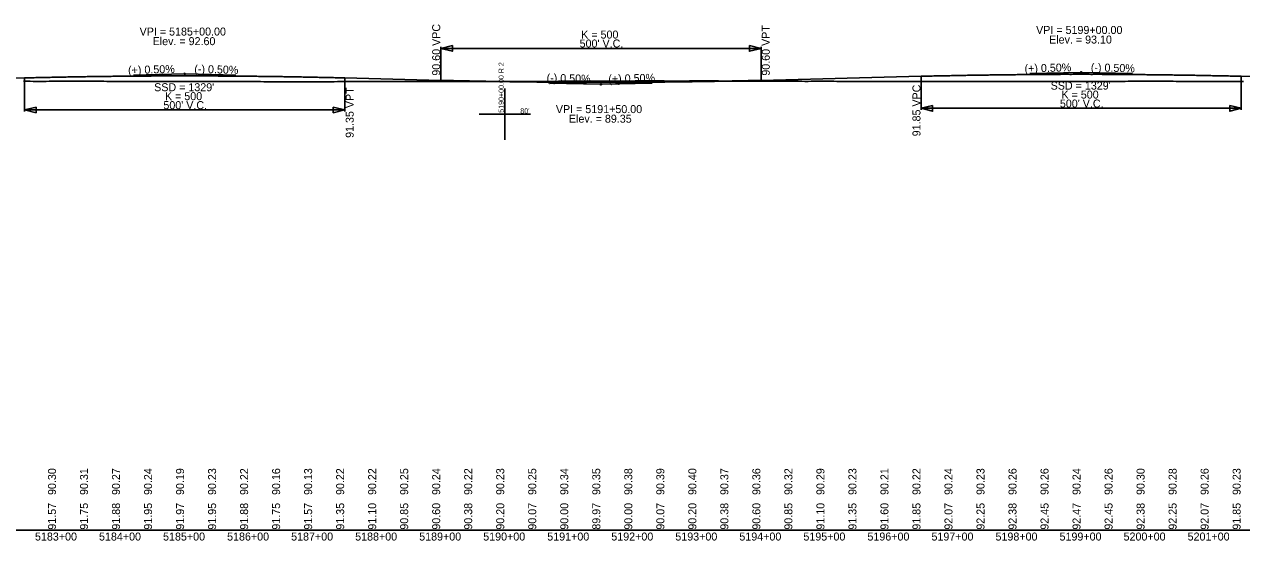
# Model space of a CAD drawing. Extents: x 2147288 to 2220488, y 740833 to 759333.
# Drawn here: x 2150631 to 2152532, y 758067 to 758874 of the extents above; entities that cross this region are included whole.
import ezdxf

# ---------------------------------------------------------------- set-up
doc = ezdxf.new("R2010")
doc.units = 0
for name, color, linetype in [('RD_DDB_GradeTX', 7, 'Continuous'), ('RD_DDB_Profile_EX', 7, 'Continuous'), ('RD_DDB_Profile_Lbl', 7, 'Continuous'), ('RD_DDB_Profile_PR', 7, 'Continuous'), ('RD_DDB_StaTX', 7, 'Continuous'), ('RD_DDB_StripGrade', 7, 'Continuous'), ('RD_DDB_VCLbl', 7, 'Continuous'), ('RD_GPK_Profile_Cell', 7, 'Continuous')]:
    doc.layers.add(name, color=color, linetype=linetype)

msp = doc.modelspace()

# ---------------------------------------------------------------- linework, layer by layer
at = {"layer": 'RD_DDB_GradeTX'}
for p, q in [((2150801.1, 758794.4), (2150880.1, 758796.4)), ((2150961.1, 758794.4), (2150882.1, 758796.4)), ((2152201.1, 758796.9), (2152280.1, 758798.9)), ((2152361.1, 758796.9), (2152282.1, 758798.9)), ((2151451.1, 758782.2), (2151530.1, 758780.2)), ((2151611.1, 758782.2), (2151532.1, 758780.2))]:
    msp.add_line(p, q, dxfattribs=at)
for centre in [(2150881.1, 758796.4), (2152281.1, 758798.9), (2151531.1, 758780.2)]:
    msp.add_circle(centre, 1, dxfattribs=at)
at = {"layer": 'RD_DDB_Profile_EX'}
for points in [[(2150629.6, 758784.9), (2150634.6, 758784.9), (2150639.6, 758784.9), (2150644.6, 758784.8), (2150649.6, 758784.8), (2150654.6, 758784.8), (2150659.6, 758784.8), (2150664.6, 758784.8), (2150669.6, 758784.9), (2150674.6, 758784.9), (2150679.6, 758784.9), (2150684.6, 758785), (2150689.6, 758785), (2150694.6, 758785), (2150699.6, 758785), (2150704.6, 758785), (2150709.6, 758785), (2150714.6, 758785), (2150719.6, 758785), (2150724.6, 758785), (2150729.6, 758785), (2150734.6, 758785), (2150739.6, 758784.9), (2150744.6, 758784.9), (2150749.6, 758784.9), (2150754.6, 758784.9), (2150759.6, 758784.8), (2150764.6, 758784.8), (2150769.6, 758784.8), (2150774.6, 758784.8), (2150779.6, 758784.8), (2150784.6, 758784.8), (2150789.6, 758784.8), (2150794.6, 758784.8), (2150799.6, 758784.8), (2150804.6, 758784.8), (2150809.6, 758784.8), (2150814.6, 758784.8), (2150819.6, 758784.7), (2150824.6, 758784.7), (2150829.6, 758784.6), (2150834.6, 758784.6), (2150839.6, 758784.5), (2150844.6, 758784.5), (2150849.6, 758784.4), (2150854.6, 758784.4), (2150859.6, 758784.4), (2150864.6, 758784.4), (2150869.6, 758784.4), (2150874.6, 758784.4), (2150879.6, 758784.4), (2150884.6, 758784.4), (2150889.6, 758784.4), (2150894.6, 758784.4), (2150899.6, 758784.4), (2150904.6, 758784.5), (2150909.6, 758784.5), (2150914.6, 758784.5), (2150919.6, 758784.5), (2150924.6, 758784.5), (2150929.6, 758784.6), (2150934.6, 758784.6), (2150939.6, 758784.6), (2150944.6, 758784.6), (2150949.6, 758784.6), (2150954.6, 758784.6), (2150959.6, 758784.6), (2150964.6, 758784.6), (2150969.6, 758784.6), (2150974.6, 758784.6), (2150979.6, 758784.5), (2150984.6, 758784.5), (2150989.6, 758784.4), (2150994.6, 758784.4), (2150999.6, 758784.4), (2151004.6, 758784.3), (2151009.6, 758784.3), (2151014.6, 758784.2), (2151019.6, 758784.2), (2151024.6, 758784.2), (2151029.6, 758784.2), (2151034.6, 758784.2)], [(2151034.6, 758784.2), (2151039.6, 758784.2), (2151044.6, 758784.2), (2151049.6, 758784.2), (2151054.6, 758784.2), (2151059.6, 758784.2), (2151064.6, 758784.2), (2151069.6, 758784.1), (2151074.6, 758784.1), (2151079.6, 758784.1), (2151084.6, 758784.1), (2151089.6, 758784.1), (2151094.6, 758784.1), (2151099.6, 758784.1), (2151104.6, 758784.2), (2151109.6, 758784.3), (2151114.6, 758784.3), (2151119.6, 758784.4), (2151124.6, 758784.5), (2151129.6, 758784.5), (2151134.6, 758784.6), (2151139.6, 758784.6), (2151144.6, 758784.6), (2151149.6, 758784.5), (2151154.6, 758784.5), (2151159.6, 758784.5), (2151164.6, 758784.5), (2151169.6, 758784.5), (2151174.6, 758784.5), (2151179.6, 758784.5), (2151184.6, 758784.5), (2151189.6, 758784.6), (2151194.6, 758784.6), (2151199.6, 758784.7), (2151204.6, 758784.7), (2151209.6, 758784.8), (2151214.6, 758784.8), (2151219.6, 758784.7), (2151224.6, 758784.7), (2151229.6, 758784.7), (2151234.6, 758784.6), (2151239.6, 758784.6), (2151244.6, 758784.6), (2151249.6, 758784.6), (2151254.6, 758784.5), (2151259.6, 758784.6), (2151264.6, 758784.6), (2151269.6, 758784.6), (2151274.6, 758784.6), (2151279.6, 758784.6), (2151284.6, 758784.6), (2151289.6, 758784.7), (2151294.6, 758784.7), (2151299.6, 758784.6), (2151304.6, 758784.6), (2151309.6, 758784.6), (2151314.6, 758784.6), (2151319.6, 758784.6), (2151324.6, 758784.5), (2151329.6, 758784.5), (2151334.6, 758784.5), (2151339.6, 758784.5), (2151344.6, 758784.5), (2151349.6, 758784.5), (2151354.6, 758784.5), (2151359.6, 758784.5), (2151364.6, 758784.5), (2151369.6, 758784.5), (2151374.6, 758784.5), (2151379.6, 758784.6), (2151384.6, 758784.6), (2151389.6, 758784.6), (2151394.6, 758784.6), (2151399.6, 758784.6), (2151404.6, 758784.6), (2151409.6, 758784.6), (2151414.6, 758784.7), (2151419.6, 758784.7), (2151424.6, 758784.7), (2151429.6, 758784.7), (2151434.6, 758784.7), (2151439.6, 758784.7), (2151444.6, 758784.7), (2151449.6, 758784.7), (2151454.6, 758784.8), (2151459.6, 758784.8), (2151464.6, 758784.9), (2151469.6, 758785), (2151474.6, 758785), (2151479.6, 758785.1), (2151484.6, 758785.2), (2151489.6, 758785.2), (2151494.6, 758785.3), (2151499.6, 758785.3), (2151504.6, 758785.2), (2151509.6, 758785.2), (2151514.6, 758785.2), (2151519.6, 758785.2), (2151524.6, 758785.2), (2151529.6, 758785.2), (2151534.6, 758785.2)], [(2151534.6, 758785.2), (2151539.6, 758785.2), (2151544.6, 758785.2), (2151549.6, 758785.2), (2151554.6, 758785.3), (2151559.6, 758785.3), (2151564.6, 758785.3), (2151569.6, 758785.3), (2151574.6, 758785.3), (2151579.6, 758785.3), (2151584.6, 758785.4), (2151589.6, 758785.4), (2151594.6, 758785.4), (2151599.6, 758785.4), (2151604.6, 758785.4), (2151609.6, 758785.4), (2151614.6, 758785.4), (2151619.6, 758785.4), (2151624.6, 758785.4), (2151629.6, 758785.4), (2151634.6, 758785.3), (2151639.6, 758785.3), (2151644.6, 758785.3), (2151649.6, 758785.3), (2151654.6, 758785.3), (2151659.6, 758785.3), (2151664.6, 758785.3), (2151669.6, 758785.4), (2151674.6, 758785.4), (2151679.6, 758785.4), (2151684.6, 758785.5), (2151689.6, 758785.5), (2151694.6, 758785.5), (2151699.6, 758785.5), (2151704.6, 758785.4), (2151709.6, 758785.4), (2151714.6, 758785.4), (2151719.6, 758785.3), (2151724.6, 758785.3), (2151729.6, 758785.3), (2151734.6, 758785.3), (2151739.6, 758785.3), (2151744.6, 758785.3), (2151749.6, 758785.3), (2151754.6, 758785.3), (2151759.6, 758785.3), (2151764.6, 758785.3), (2151769.6, 758785.2), (2151774.6, 758785.2), (2151779.6, 758785.2), (2151784.6, 758785.2), (2151789.6, 758785.2), (2151794.6, 758785.2), (2151799.6, 758785.2), (2151804.6, 758785.2), (2151809.6, 758785.2), (2151814.6, 758785.2), (2151819.6, 758785.1), (2151824.6, 758785.1), (2151829.6, 758785), (2151834.6, 758785), (2151839.6, 758784.9), (2151844.6, 758784.9), (2151849.6, 758784.8), (2151854.6, 758784.8), (2151859.6, 758784.9), (2151864.6, 758784.9), (2151869.6, 758784.9), (2151874.6, 758784.9), (2151879.6, 758784.9), (2151884.6, 758784.9), (2151889.6, 758784.9), (2151894.6, 758784.9), (2151899.6, 758784.8), (2151904.6, 758784.8), (2151909.6, 758784.8), (2151914.6, 758784.7), (2151919.6, 758784.7), (2151924.6, 758784.6), (2151929.6, 758784.6), (2151934.6, 758784.6), (2151939.6, 758784.5), (2151944.6, 758784.5), (2151949.6, 758784.5), (2151954.6, 758784.5), (2151959.6, 758784.5), (2151964.6, 758784.5), (2151969.6, 758784.4), (2151974.6, 758784.4), (2151979.6, 758784.4), (2151984.6, 758784.5), (2151989.6, 758784.5), (2151994.6, 758784.5), (2151999.6, 758784.5), (2152004.6, 758784.5), (2152009.6, 758784.5), (2152014.6, 758784.5), (2152019.6, 758784.5), (2152024.6, 758784.5), (2152029.6, 758784.5), (2152034.6, 758784.6)], [(2152034.6, 758784.6), (2152039.6, 758784.6), (2152044.6, 758784.6), (2152049.6, 758784.6), (2152054.6, 758784.6), (2152059.6, 758784.6), (2152064.6, 758784.6), (2152069.6, 758784.6), (2152074.6, 758784.6), (2152079.6, 758784.6), (2152084.6, 758784.6), (2152089.6, 758784.7), (2152094.6, 758784.6), (2152099.6, 758784.6), (2152104.6, 758784.6), (2152109.6, 758784.6), (2152114.6, 758784.6), (2152119.6, 758784.6), (2152124.6, 758784.6), (2152129.6, 758784.6), (2152134.6, 758784.6), (2152139.6, 758784.6), (2152144.6, 758784.6), (2152149.6, 758784.6), (2152154.6, 758784.7), (2152159.6, 758784.7), (2152164.6, 758784.7), (2152169.6, 758784.7), (2152174.6, 758784.7), (2152179.6, 758784.7), (2152184.6, 758784.7), (2152189.6, 758784.7), (2152194.6, 758784.8), (2152199.6, 758784.8), (2152204.6, 758784.8), (2152209.6, 758784.8), (2152214.6, 758784.8), (2152219.6, 758784.8), (2152224.6, 758784.7), (2152229.6, 758784.7), (2152234.6, 758784.7), (2152239.6, 758784.7), (2152244.6, 758784.7), (2152249.6, 758784.6), (2152254.6, 758784.6), (2152259.6, 758784.6), (2152264.6, 758784.6), (2152269.6, 758784.6), (2152274.6, 758784.6), (2152279.6, 758784.6), (2152284.6, 758784.6), (2152289.6, 758784.6), (2152294.6, 758784.6), (2152299.6, 758784.6), (2152304.6, 758784.6), (2152309.6, 758784.7), (2152314.6, 758784.7), (2152319.6, 758784.7), (2152324.6, 758784.7), (2152329.6, 758784.7), (2152334.6, 758784.7), (2152339.6, 758784.8), (2152344.6, 758784.8), (2152349.6, 758784.8), (2152354.6, 758784.9), (2152359.6, 758784.9), (2152364.6, 758784.9), (2152369.6, 758784.9), (2152374.6, 758784.9), (2152379.6, 758784.9), (2152384.6, 758784.9), (2152389.6, 758784.9), (2152394.6, 758784.9), (2152399.6, 758784.9), (2152404.6, 758784.9), (2152409.6, 758785), (2152414.6, 758784.9), (2152419.6, 758784.9), (2152424.6, 758784.9), (2152429.6, 758784.8), (2152434.6, 758784.8), (2152439.6, 758784.8), (2152444.6, 758784.8), (2152449.6, 758784.8), (2152454.6, 758784.8), (2152459.6, 758784.7), (2152464.6, 758784.7), (2152469.6, 758784.7), (2152474.6, 758784.7), (2152479.6, 758784.7), (2152484.6, 758784.7), (2152489.6, 758784.7), (2152494.6, 758784.7), (2152499.6, 758784.6), (2152504.6, 758784.6), (2152509.6, 758784.6), (2152514.6, 758784.6), (2152519.6, 758784.6), (2152524.6, 758784.6), (2152529.6, 758784.6), (2152534.6, 758784.5)]]:
    msp.add_lwpolyline(points, dxfattribs=at)
at = {"layer": 'RD_DDB_Profile_PR'}
for p, q in [((2150481.1, 758786.4), (2150631.1, 758790.2)), ((2151131.1, 758790.2), (2151281.1, 758786.4)), ((2151781.1, 758786.4), (2152031.1, 758792.7)), ((2152531.1, 758792.7), (2152781.1, 758786.4))]:
    msp.add_line(p, q, dxfattribs=at)
for points in [[(2150631.1, 758790.2), (2150641.1, 758790.4), (2150651.1, 758790.7), (2150661.1, 758790.9), (2150671.1, 758791.1), (2150681.1, 758791.3), (2150691.1, 758791.5), (2150701.1, 758791.7), (2150711.1, 758791.9), (2150721.1, 758792), (2150731.1, 758792.2), (2150741.1, 758792.3), (2150751.1, 758792.5), (2150761.1, 758792.6), (2150771.1, 758792.7), (2150781.1, 758792.8), (2150791.1, 758792.9), (2150801.1, 758793), (2150811.1, 758793.1), (2150821.1, 758793.1), (2150831.1, 758793.2), (2150841.1, 758793.2), (2150851.1, 758793.3), (2150861.1, 758793.3), (2150871.1, 758793.3), (2150881.1, 758793.3), (2150891.1, 758793.3), (2150901.1, 758793.3), (2150911.1, 758793.3), (2150921.1, 758793.2), (2150931.1, 758793.2), (2150941.1, 758793.1), (2150951.1, 758793.1), (2150961.1, 758793), (2150971.1, 758792.9), (2150981.1, 758792.8), (2150991.1, 758792.7), (2151001.1, 758792.6), (2151011.1, 758792.5), (2151021.1, 758792.3), (2151031.1, 758792.2), (2151041.1, 758792), (2151051.1, 758791.9), (2151061.1, 758791.7), (2151071.1, 758791.5), (2151081.1, 758791.3), (2151091.1, 758791.1), (2151101.1, 758790.9), (2151111.1, 758790.7), (2151121.1, 758790.4), (2151131.1, 758790.2)], [(2152031.1, 758792.7), (2152041.1, 758792.9), (2152051.1, 758793.2), (2152061.1, 758793.4), (2152071.1, 758793.6), (2152081.1, 758793.8), (2152091.1, 758794), (2152101.1, 758794.2), (2152111.1, 758794.4), (2152121.1, 758794.5), (2152131.1, 758794.7), (2152141.1, 758794.8), (2152151.1, 758795), (2152161.1, 758795.1), (2152171.1, 758795.2), (2152181.1, 758795.3), (2152191.1, 758795.4), (2152201.1, 758795.5), (2152211.1, 758795.6), (2152221.1, 758795.6), (2152231.1, 758795.7), (2152241.1, 758795.7), (2152251.1, 758795.8), (2152261.1, 758795.8), (2152271.1, 758795.8), (2152281.1, 758795.8), (2152291.1, 758795.8), (2152301.1, 758795.8), (2152311.1, 758795.8), (2152321.1, 758795.7), (2152331.1, 758795.7), (2152341.1, 758795.6), (2152351.1, 758795.6), (2152361.1, 758795.5), (2152371.1, 758795.4), (2152381.1, 758795.3), (2152391.1, 758795.2), (2152401.1, 758795.1), (2152411.1, 758795), (2152421.1, 758794.8), (2152431.1, 758794.7), (2152441.1, 758794.5), (2152451.1, 758794.4), (2152461.1, 758794.2), (2152471.1, 758794), (2152481.1, 758793.8), (2152491.1, 758793.6), (2152501.1, 758793.4), (2152511.1, 758793.2), (2152521.1, 758792.9), (2152531.1, 758792.7)], [(2151281.1, 758786.4), (2151291.1, 758786.2), (2151301.1, 758785.9), (2151311.1, 758785.7), (2151321.1, 758785.5), (2151331.1, 758785.3), (2151341.1, 758785.1), (2151351.1, 758784.9), (2151361.1, 758784.7), (2151371.1, 758784.6), (2151381.1, 758784.4), (2151391.1, 758784.3), (2151401.1, 758784.1), (2151411.1, 758784), (2151421.1, 758783.9), (2151431.1, 758783.8), (2151441.1, 758783.7), (2151451.1, 758783.6), (2151461.1, 758783.5), (2151471.1, 758783.5), (2151481.1, 758783.4), (2151491.1, 758783.4), (2151501.1, 758783.3), (2151511.1, 758783.3), (2151521.1, 758783.3), (2151531.1, 758783.3), (2151541.1, 758783.3), (2151551.1, 758783.3), (2151561.1, 758783.3), (2151571.1, 758783.4), (2151581.1, 758783.4), (2151591.1, 758783.5), (2151601.1, 758783.5), (2151611.1, 758783.6), (2151621.1, 758783.7), (2151631.1, 758783.8), (2151641.1, 758783.9), (2151651.1, 758784), (2151661.1, 758784.1), (2151671.1, 758784.3), (2151681.1, 758784.4), (2151691.1, 758784.6), (2151701.1, 758784.7), (2151711.1, 758784.9), (2151721.1, 758785.1), (2151731.1, 758785.3), (2151741.1, 758785.5), (2151751.1, 758785.7), (2151761.1, 758785.9), (2151771.1, 758786.2), (2151781.1, 758786.4)]]:
    msp.add_spline(points, degree=3, dxfattribs=at)
at = {"layer": 'RD_DDB_VCLbl'}
for p, q in [((2151281.1, 758838.9), (2151281.1, 758786.4)), ((2151281.1, 758836.4), (2151781.1, 758836.4)), ((2151781.1, 758838.9), (2151781.1, 758786.4)), ((2150631.1, 758737.7), (2150631.1, 758790.2)), ((2151131.1, 758737.7), (2151131.1, 758790.2)), ((2152031.1, 758740.2), (2152031.1, 758792.7)), ((2152531.1, 758740.2), (2152531.1, 758792.7)), ((2150631.1, 758740.2), (2151131.1, 758740.2)), ((2152031.1, 758742.7), (2152531.1, 758742.7))]:
    msp.add_line(p, q, dxfattribs=at)
for points in [[(2151299.1, 758840.9), (2151281.1, 758836.4), (2151299.1, 758831.9)], [(2151763.1, 758840.9), (2151781.1, 758836.4), (2151763.1, 758831.9)], [(2150649.1, 758744.7), (2150631.1, 758740.2), (2150649.1, 758735.7)], [(2151113.1, 758744.7), (2151131.1, 758740.2), (2151113.1, 758735.7)], [(2152049.1, 758747.2), (2152031.1, 758742.7), (2152049.1, 758738.2)], [(2152513.1, 758747.2), (2152531.1, 758742.7), (2152513.1, 758738.2)]]:
    msp.add_lwpolyline(points, close=True, dxfattribs=at)
at = {"layer": 'RD_GPK_Profile_Cell'}
for p, q in [((2151381.1, 758773.4), (2151381.1, 758693.4)), ((2151421.1, 758733.4), (2151341.1, 758733.4)), ((2148888.3, 758083.4), (2165888.3, 758083.4))]:
    msp.add_line(p, q, dxfattribs=at)

# ---------------------------------------------------------------- texts
at = {"layer": 'RD_DDB_GradeTX'}
for s, rotation, p in [('(+) 0.50%', 1.4321, (2150792.8, 758796.2)), ('(-) 0.50%', 358.5679, (2150896, 758798.1)), ('(+) 0.50%', 1.4321, (2152192.8, 758798.7)), ('(-) 0.50%', 358.5679, (2152296, 758800.6)), ('(-) 0.50%', 358.5679, (2151446.1, 758784.3)), ('(+) 0.50%', 1.4321, (2151542.8, 758782.5))]:
    msp.add_text(s, height=12.5, rotation=rotation, dxfattribs=at).set_placement(p)
at = {"layer": 'RD_DDB_Profile_Lbl'}
for s, p in [('VPI = 5185+00.00', (2150810.7, 758856.4)), ('VPI = 5199+00.00', (2152210.7, 758858.9)), ('Elev. = 92.60', (2150831, 758841.4)), ('Elev. = 93.10', (2152231, 758843.9)), ('VPI = 5191+50.00', (2151460.7, 758735.2)), ('Elev. = 89.35', (2151481.1, 758720.2))]:
    msp.add_text(s, height=12.5, dxfattribs=at).set_placement(p)
at = {"layer": 'RD_DDB_StaTX'}
for s, p in [('5183+00', (2150647.3, 758067.2)), ('5184+00', (2150747.3, 758067.2)), ('5185+00', (2150847.3, 758067.2)), ('5186+00', (2150947.3, 758067.2)), ('5187+00', (2151047.3, 758067.2)), ('5188+00', (2151147.3, 758067.2)), ('5189+00', (2151247.3, 758067.2)), ('5190+00', (2151347.3, 758067.2)), ('5191+00', (2151447.3, 758067.2)), ('5192+00', (2151547.3, 758067.2)), ('5193+00', (2151647.3, 758067.2)), ('5194+00', (2151747.3, 758067.2)), ('5195+00', (2151847.3, 758067.2)), ('5196+00', (2151947.3, 758067.2)), ('5197+00', (2152047.3, 758067.2)), ('5198+00', (2152147.3, 758067.2)), ('5199+00', (2152247.3, 758067.2)), ('5200+00', (2152347.3, 758067.2)), ('5201+00', (2152447.3, 758067.2))]:
    msp.add_text(s, height=12.5, dxfattribs=at).set_placement(p)
at = {"layer": 'RD_DDB_StripGrade'}
for s, p in [('90.60 VPC', (2151280.1, 758793.7)), ('90.60 VPT', (2151794.8, 758793.7)), ('91.35 VPT', (2151145, 758696.5)), ('91.85 VPC', (2152030.1, 758698.9)), ('90.30', (2150680.1, 758138.4)), ('90.31', (2150730.1, 758138.4)), ('90.27', (2150780.1, 758138.4)), ('90.24', (2150830.1, 758138.4)), ('90.19', (2150880.1, 758138.4)), ('90.23', (2150930.1, 758138.4)), ('90.22', (2150980.1, 758138.4)), ('90.16', (2151030.1, 758138.4)), ('90.13', (2151080.1, 758138.4)), ('90.22', (2151130.1, 758138.4)), ('90.22', (2151180.1, 758138.4)), ('90.25', (2151230.1, 758138.4)), ('90.24', (2151280.1, 758138.4)), ('90.22', (2151330.1, 758138.4)), ('90.23', (2151380.1, 758138.4)), ('90.25', (2151430.1, 758138.4)), ('90.34', (2151480.1, 758138.4)), ('90.35', (2151530.1, 758138.4)), ('90.38', (2151580.1, 758138.4)), ('90.39', (2151630.1, 758138.4)), ('90.40', (2151680.1, 758138.4)), ('90.37', (2151730.1, 758138.4)), ('90.36', (2151780.1, 758138.4)), ('90.32', (2151830.1, 758138.4)), ('90.29', (2151880.1, 758138.4)), ('90.23', (2151930.1, 758138.4)), ('90.21', (2151980.1, 758138.4)), ('90.22', (2152030.1, 758138.4)), ('90.24', (2152080.1, 758138.4)), ('90.23', (2152130.1, 758138.4)), ('90.26', (2152180.1, 758138.4)), ('90.26', (2152230.1, 758138.4)), ('90.24', (2152280.1, 758138.4)), ('90.26', (2152330.1, 758138.4)), ('90.30', (2152380.1, 758138.4)), ('90.28', (2152430.1, 758138.4)), ('90.26', (2152480.1, 758138.4)), ('90.23', (2152530.1, 758138.4)), ('91.57', (2150680.1, 758084.2)), ('91.75', (2150730.1, 758084.2)), ('91.88', (2150780.1, 758084.2)), ('91.95', (2150830.1, 758084.2)), ('91.97', (2150880.1, 758084.2)), ('91.95', (2150930.1, 758084.2)), ('91.88', (2150980.1, 758084.2)), ('91.75', (2151030.1, 758084.2)), ('91.57', (2151080.1, 758084.2)), ('91.35', (2151130.1, 758084.2)), ('91.10', (2151180.1, 758084.2)), ('90.85', (2151230.1, 758084.2)), ('90.60', (2151280.1, 758084.2)), ('90.38', (2151330.1, 758084.2)), ('90.20', (2151380.1, 758084.2)), ('90.07', (2151430.1, 758084.2)), ('90.00', (2151480.1, 758084.2)), ('89.97', (2151530.1, 758084.2)), ('90.00', (2151580.1, 758084.2)), ('90.07', (2151630.1, 758084.2)), ('90.20', (2151680.1, 758084.2)), ('90.38', (2151730.1, 758084.2)), ('90.60', (2151780.1, 758084.2)), ('90.85', (2151830.1, 758084.2)), ('91.10', (2151880.1, 758084.2)), ('91.35', (2151930.1, 758084.2)), ('91.60', (2151980.1, 758084.2)), ('91.85', (2152030.1, 758084.2)), ('92.07', (2152080.1, 758084.2)), ('92.25', (2152130.1, 758084.2)), ('92.38', (2152180.1, 758084.2)), ('92.45', (2152230.1, 758084.2)), ('92.47', (2152280.1, 758084.2)), ('92.45', (2152330.1, 758084.2)), ('92.38', (2152380.1, 758084.2)), ('92.25', (2152430.1, 758084.2)), ('92.07', (2152480.1, 758084.2)), ('91.85', (2152530.1, 758084.2))]:
    msp.add_text(s, height=12.5, rotation=90, dxfattribs=at).set_placement(p)
at = {"layer": 'RD_DDB_VCLbl'}
for s, p in [('K = 500', (2151500.3, 758851.7)), ("500' V.C.", (2151497.8, 758837.7)), ("SSD = 1329'", (2150833.4, 758769.4)), ("SSD = 1329'", (2152233.4, 758771.9)), ('K = 500', (2152250.3, 758757.9)), ("500' V.C.", (2150847.8, 758741.4)), ('K = 500', (2150850.3, 758755.4)), ("500' V.C.", (2152247.8, 758743.9))]:
    msp.add_text(s, height=12.5, dxfattribs=at).set_placement(p)
at = {"layer": 'RD_GPK_Profile_Cell'}
msp.add_text('5190+00.00 R 2', height=8, rotation=90, dxfattribs=at).set_placement((2151379.3, 758735.8))
msp.add_text("80'", height=8, dxfattribs=at).set_placement((2151405.2, 758734.6))

doc.saveas('drawing.dxf')
